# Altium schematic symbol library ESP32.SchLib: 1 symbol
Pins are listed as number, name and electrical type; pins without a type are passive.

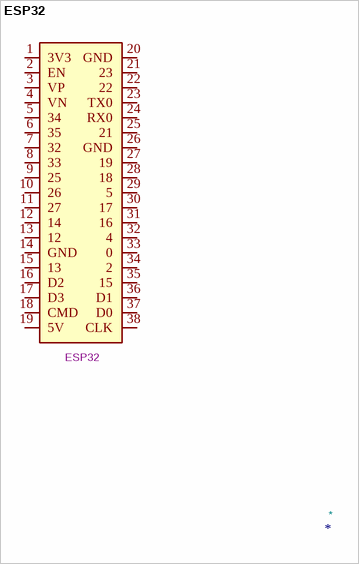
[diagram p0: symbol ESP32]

## ESP32
designator *  Reference: ESP32
pins: 1 3V3, 2 EN, 3 VP, 4 VN, 5 34, 6 35, 7 32, 8 33, 9 25, 10 26, 11 27, 12 14, 13 12, 14 GND, 15 13, 16 D2, 17 D3, 18 CMD, 19 5V, 20 GND, 21 23, 22, 23 TX0, 24 RX0, 25 21, 26 GND, 27 19, 28 18, 29 5, 30 17, 31 16, 32 4, 33 0, 34 2, 35 15, 36 D1, 37 D0, 38 CLK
